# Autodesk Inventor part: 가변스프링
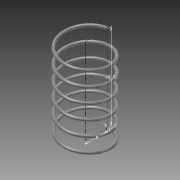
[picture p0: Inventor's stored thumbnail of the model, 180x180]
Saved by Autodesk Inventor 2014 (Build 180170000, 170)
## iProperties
Created: 2016-12
Part Number: 가변스프링
Material: Stainless Steel
Document SubType Name: Modeling
Designer: user
Density: 8.08 g/cm^3
Appearance: Semi-Polished
Mass: 1.91391 g
Surface Area: 9.51473 cm^2
Volume: 0.236871 cm^3
Author: user
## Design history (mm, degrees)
sketch "Sketch1"
  geometry: L1 (0, 0)-(8, 0); L2 (8, 0)-(8, 30.5); L3 (8, 30.5)-(0, 30.5); L4 (0, 30.5)-(0, 0); C1 r 0.5 at (8, 0)
  constraints: 8 end point, 2 parallel, 1 centre point, 1 coincident, 1 horizontal, 1 perpendicular
  dimensions: "d0" = 1 diameter of C1; "d1" = 8 distance of L1.start L1.end; "d2" = 30.5 distance of L1.end L2.end (derived)
coil "Coil1" pitch "d3" = 10; turns "d5" = 6; dims "d4" = 30.5 (= d2), "d6" = 0, angle "d7" = 90 deg, angle "d8" = 90 deg, "d9" = 0, "d10" = 0
body "Solid1"
